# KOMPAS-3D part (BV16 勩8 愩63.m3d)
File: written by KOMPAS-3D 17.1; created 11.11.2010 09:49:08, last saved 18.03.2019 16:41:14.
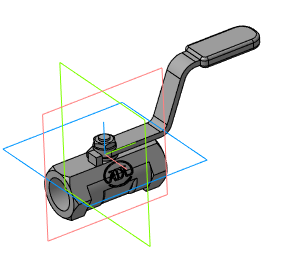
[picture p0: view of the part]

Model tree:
1. Плоскость XY
2. Плоскость ZX
3. Плоскость ZY
4. Ось X
5. Ось Y
6. Ось Z
7. Начало координат
8. Операция без истории:1

Referenced files in \\adlc.lan\data\АДЛ_ПКД\3D-модели\ADL production\Краны шаровые серии BV\BV16\: шаровый кран BV16 Ду15.a3d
